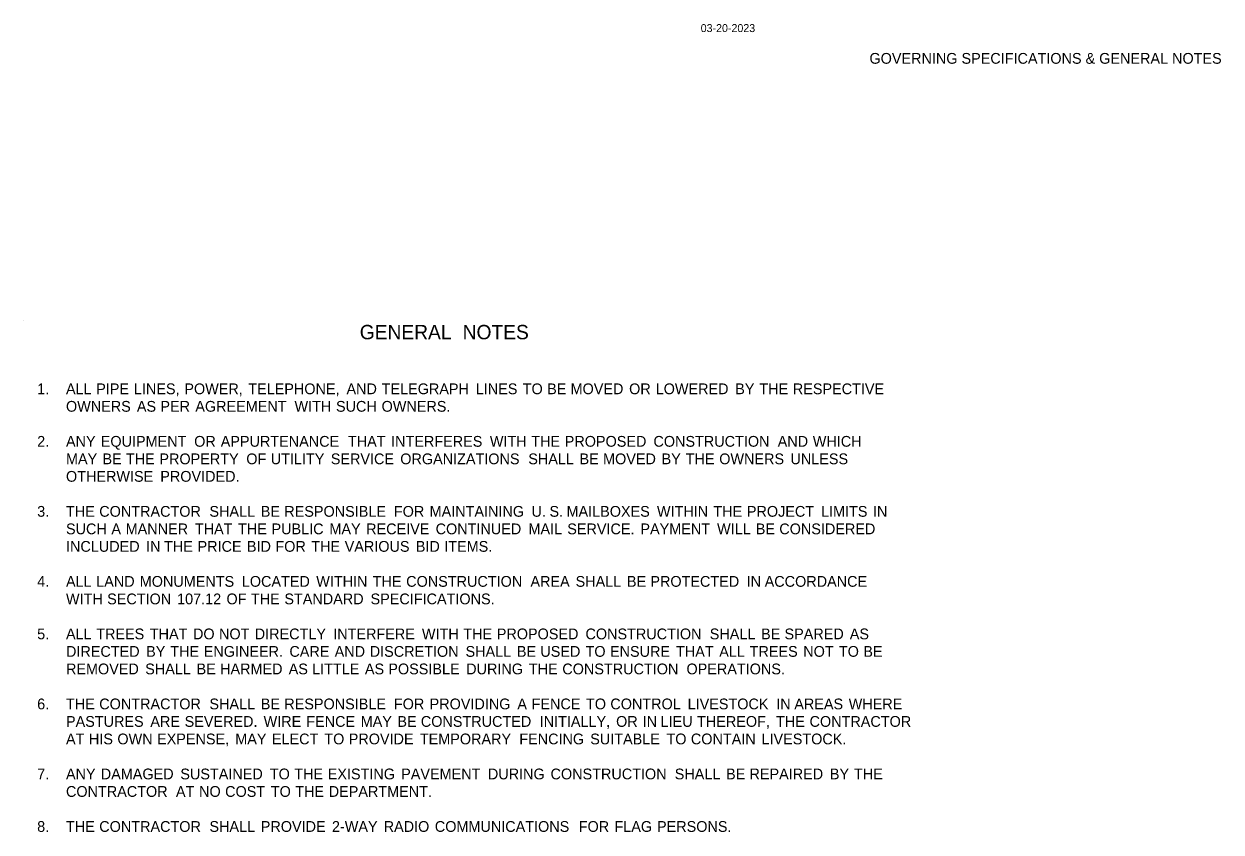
# Model space of a CAD drawing. Extents: x -1218 to 1646, y -1033 to 999.
# Drawn here: x 313 to 1646, y 98 to 999 of the extents above; entities that cross this region are included whole.
import ezdxf

# ---------------------------------------------------------------- set-up
doc = ezdxf.new("R2010")
doc.units = 0
doc.layers.add('Default', color=7, linetype='Continuous')
doc.layers.add('R_Border Prem', color=7, linetype='Continuous')

msp = doc.modelspace()

# ---------------------------------------------------------------- linework, layer by layer
at = {"layer": 'Default'}
msp.add_line((312.6, 668.5), (312.6, 668.5), dxfattribs=at)

# ---------------------------------------------------------------- texts
for s, height, p in [('GENERAL', 16, (686.6, 647.3)), (' NOTES', 16, (795.3, 647.3)), ('1.', 12, (327.3, 586.1)), ('ALL', 12, (359.4, 586.1)), (' PIPE', 12, (388.6, 586.1)), (' LINES,', 12, (430.6, 586.1)), (' POWER,', 12, (486.8, 586.1)), (' TELEPHONE,', 12, (558, 586.1)), (' AND', 12, (667.4, 586.1)), (' TELEGRAPH', 12, (706.6, 586.1)), (' LINES', 12, (811.4, 586.1)), (' TO', 12, (863.7, 586.1)), (' BE', 12, (890.9, 586.1)), (' MOVED', 12, (917, 586.1)), (' OR', 12, (982.2, 586.1)), (' LOWERED', 12, (1011.8, 586.1)), (' BY', 12, (1100.4, 586.1)), (' THE', 12, (1127.3, 586.1)), (' RESPECTIVE', 12, (1164.6, 586.1)), ('OWNERS', 12, (359.4, 566.6)), (' AS', 12, (433.9, 566.6)), (' PER', 12, (460.1, 566.6)), (' AGREEMENT', 12, (499, 566.6)), (' WITH', 12, (609.5, 566.6)), (' SUCH', 12, (655.7, 566.6)), (' OWNERS.', 12, (706.5, 566.6)), ('2.', 12, (327.3, 527.6)), ('ANY', 12, (359.4, 527.6)), (' EQUIPMENT', 12, (393.7, 527.6)), (' OR', 12, (497.7, 527.6)), (' APPURTENANCE', 12, (527.3, 527.6)), (' THAT', 12, (669, 527.6)), (' INTERFERES', 12, (717.1, 527.6)), (' WITH', 12, (827.1, 527.6)), (' THE', 12, (873.2, 527.6)), (' PROPOSED', 12, (910.5, 527.6)), (' CONSTRUCTION', 12, (1009.3, 527.6)), (' AND', 12, (1147.7, 527.6)), (' WHICH', 12, (1186.8, 527.6)), ('MAY', 12, (359.4, 508.1)), (' BE', 12, (395.6, 508.1)), (' THE', 12, (421.7, 508.1)), (' PROPERTY', 12, (459, 508.1)), (' OF', 12, (555.8, 508.1)), (' UTILITY', 12, (583, 508.1)), (' SERVICE', 12, (649.9, 508.1)), (' ORGANIZATIONS', 12, (727.3, 508.1)), (' SHALL', 12, (869.9, 508.1)), (' BE', 12, (927, 508.1)), (' MOVED', 12, (953.2, 508.1)), (' BY', 12, (1018.4, 508.1)), (' THE', 12, (1045.3, 508.1)), (' OWNERS', 12, (1082.6, 508.1)), (' UNLESS', 12, (1161.9, 508.1)), ('OTHERWISE', 12, (359.4, 488.6)), (' PROVIDED.', 12, (460, 488.6)), ('3.', 12, (327.3, 449.6)), ('THE', 12, (359.4, 449.6)), (' CONTRACTOR', 12, (392, 449.6)), (' SHALL', 12, (514.7, 449.6)), (' BE', 12, (571.9, 449.6)), (' RESPONSIBLE', 12, (598.1, 449.6)), (' FOR', 12, (720.2, 449.6)), (' MAINTAINING', 12, (760, 449.6)), (' U.', 12, (873.5, 449.6)), (' S.', 12, (893.5, 449.6)), (' MAILBOXES', 12, (912.5, 449.6)), (' WITHIN', 12, (1013.2, 449.6)), (' THE', 12, (1076.1, 449.6)), (' PROJECT', 12, (1113.4, 449.6)), (' LIMITS', 12, (1196, 449.6)), (' IN', 12, (1253.8, 449.6)), ('SUCH', 12, (359.4, 430.1)), (' A', 12, (405.5, 430.1)), (' MANNER', 12, (421.4, 430.1)), (' THAT', 12, (498.5, 430.1)), (' THE', 12, (546.6, 430.1)), (' PUBLIC', 12, (583.9, 430.1)), (' MAY', 12, (648.4, 430.1)), (' RECEIVE', 12, (689.3, 430.1)), (' CONTINUED', 12, (766.7, 430.1)), (' MAIL', 12, (870.1, 430.1)), (' SERVICE.', 12, (913.3, 430.1)), (' PAYMENT', 12, (994.8, 430.1)), (' WILL', 12, (1080.2, 430.1)), (' BE', 12, (1123.3, 430.1)), (' CONSIDERED', 12, (1149.5, 430.1)), ('INCLUDED', 12, (359.4, 410.6)), (' IN', 12, (444.2, 410.6)), (' THE', 12, (464.2, 410.6)), (' PRICE', 12, (501.5, 410.6)), (' BID', 12, (556.5, 410.6)), (' FOR', 12, (588.2, 410.6)), (' THE', 12, (628.1, 410.6)), (' VARIOUS', 12, (665.4, 410.6)), (' BID', 12, (744.6, 410.6)), (' ITEMS.', 12, (776.3, 410.6)), ('4.', 12, (327.3, 371.6)), ('ALL', 12, (359.4, 371.6)), (' LAND', 12, (388.6, 371.6)), (' MONUMENTS', 12, (437.1, 371.6)), (' LOCATED', 12, (550.8, 371.6)), (' WITHIN', 12, (633.7, 371.6)), (' THE', 12, (696.6, 371.6)), (' CONSTRUCTION', 12, (733.9, 371.6)), (' AREA', 12, (872.3, 371.6)), (' SHALL', 12, (922.6, 371.6)), (' BE', 12, (979.8, 371.6)), (' PROTECTED', 12, (1005.9, 371.6)), (' IN', 12, (1113.1, 371.6)), (' ACCORDANCE', 12, (1133.2, 371.6)), ('WITH', 12, (359.4, 352.1)), (' SECTION', 12, (400.8, 352.1)), (' 107.12', 12, (478.7, 352.1)), (' OF', 12, (533.7, 352.1)), (' THE', 12, (560.9, 352.1)), (' STANDARD', 12, (598.2, 352.1)), (' SPECIFICATIONS.', 12, (694.2, 352.1)), ('5.', 12, (327.3, 313.1)), ('ALL', 12, (359.4, 313.1)), (' TREES', 12, (388.6, 313.1)), (' THAT', 12, (448.3, 313.1)), (' DO', 12, (496.4, 313.1)), (' NOT', 12, (525.4, 313.1)), (' DIRECTLY', 12, (565.2, 313.1)), (' INTERFERE', 12, (652.6, 313.1)), (' WITH', 12, (751.4, 313.1)), (' THE', 12, (797.5, 313.1)), (' PROPOSED', 12, (834.8, 313.1)), (' CONSTRUCTION', 12, (933.6, 313.1)), (' SHALL', 12, (1072, 313.1)), (' BE', 12, (1129.2, 313.1)), (' SPARED', 12, (1155.3, 313.1)), (' AS', 12, (1228, 313.1)), ('DIRECTED', 12, (359.4, 293.6)), (' BY', 12, (444.2, 293.6)), (' THE', 12, (471.1, 293.6)), (' ENGINEER.', 12, (508.4, 293.6)), (' CARE', 12, (603.8, 293.6)), (' AND', 12, (654.2, 293.6)), (' DISCRETION', 12, (693.3, 293.6)), (' SHALL', 12, (800, 293.6)), (' BE', 12, (857.2, 293.6)), (' USED', 12, (883.3, 293.6)), (' TO', 12, (933.7, 293.6)), (' ENSURE', 12, (960.9, 293.6)), (' THAT', 12, (1034.5, 293.6)), (' ALL', 12, (1082.6, 293.6)), (' TREES', 12, (1116.5, 293.6)), (' NOT', 12, (1176.2, 293.6)), (' TO', 12, (1215.9, 293.6)), (' BE', 12, (1243.1, 293.6)), ('REMOVED', 12, (359.4, 274.1)), (' SHALL', 12, (443.2, 274.1)), (' BE', 12, (500.4, 274.1)), (' HARMED', 12, (526.6, 274.1)), (' AS', 12, (603, 274.1)), (' LITTLE', 12, (629.1, 274.1)), (' AS', 12, (687.9, 274.1)), (' POSSIBLE', 12, (714, 274.1)), (' DURING', 12, (800.7, 274.1)), (' THE', 12, (870.5, 274.1)), (' CONSTRUCTION', 12, (907.8, 274.1)), (' OPERATIONS.', 12, (1046.1, 274.1)), ('6.', 12, (327.3, 235.1)), ('THE', 12, (359.4, 235.1)), (' CONTRACTOR', 12, (392, 235.1)), (' SHALL', 12, (514.7, 235.1)), (' BE', 12, (571.9, 235.1)), (' RESPONSIBLE', 12, (598.1, 235.1)), (' FOR', 12, (720.2, 235.1)), (' PROVIDING', 12, (760, 235.1)), (' A', 12, (857.7, 235.1)), (' FENCE', 12, (873.6, 235.1)), (' TO', 12, (934.2, 235.1)), (' CONTROL', 12, (961.3, 235.1)), (' LIVESTOCK', 12, (1047.4, 235.1)), (' IN', 12, (1146.1, 235.1)), (' AREAS', 12, (1166.2, 235.1)), (' WHERE', 12, (1226.8, 235.1)), ('PASTURES', 12, (359.4, 215.6)), (' ARE', 12, (448.9, 215.6)), (' SEVERED.', 12, (487.1, 215.6)), (' WIRE', 12, (575.1, 215.6)), (' FENCE', 12, (622.6, 215.6)), (' MAY', 12, (683.2, 215.6)), (' BE', 12, (724.1, 215.6)), (' CONSTRUCTED', 12, (750.2, 215.6)), (' INITIALLY,', 12, (882.6, 215.6)), (' OR', 12, (967.7, 215.6)), (' IN', 12, (997.3, 215.6)), (' LIEU', 12, (1017.3, 215.6)), (' THEREOF,', 12, (1057.9, 215.6)), (' THE', 12, (1145.9, 215.6)), (' CONTRACTOR', 12, (1183.2, 215.6)), ('AT', 12, (359.4, 196.1)), (' HIS', 12, (380.5, 196.1)), (' OWN', 12, (412.2, 196.1)), (' EXPENSE,', 12, (456.4, 196.1)), (' MAY', 12, (543.5, 196.1)), (' ELECT', 12, (584.3, 196.1)), (' TO', 12, (642.7, 196.1)), (' PROVIDE', 12, (669.9, 196.1)), (' TEMPORARY', 12, (749.1, 196.1)), (' FENCING', 12, (859.9, 196.1)), (' SUITABLE', 12, (938.9, 196.1)), (' TO', 12, (1023.8, 196.1)), (' CONTAIN', 12, (1051, 196.1)), (' LIVESTOCK.', 12, (1129.7, 196.1)), ('7.', 12, (327.3, 157.1)), ('ANY', 12, (359.4, 157.1)), (' DAMAGED', 12, (393.7, 157.1)), (' SUSTAINED', 12, (482.3, 157.1)), (' TO', 12, (582, 157.1)), (' THE', 12, (609.2, 157.1)), (' EXISTING', 12, (646.5, 157.1)), (' PAVEMENT', 12, (728.3, 157.1)), (' DURING', 12, (824.9, 157.1)), (' CONSTRUCTION', 12, (894.7, 157.1)), (' SHALL', 12, (1033, 157.1)), (' BE', 12, (1090.2, 157.1)), (' REPAIRED', 12, (1116.3, 157.1)), (' BY', 12, (1205.8, 157.1)), (' THE', 12, (1232.7, 157.1)), ('CONTRACTOR', 12, (359.4, 137.6)), (' AT', 12, (477.4, 137.6)), (' NO', 12, (503.2, 137.6)), (' COST', 12, (532.2, 137.6)), (' TO', 12, (583.1, 137.6)), (' THE', 12, (610.3, 137.6)), (' DEPARTMENT.', 12, (647.6, 137.6)), ('8.', 12, (327.3, 98.6)), ('THE', 12, (359.4, 98.6)), (' CONTRACTOR', 12, (392, 98.6)), (' SHALL', 12, (514.7, 98.6)), (' PROVIDE', 12, (571.9, 98.6)), (' 2-WAY', 12, (651.2, 98.6)), (' RADIO', 12, (708.8, 98.6)), (' COMMUNICATIONS', 12, (765.8, 98.6)), (' FOR', 12, (926.1, 98.6)), (' FLAG', 12, (965.9, 98.6)), (' PERSONS.', 12, (1013.3, 98.6))]:
    msp.add_text(s, height=height, dxfattribs=at).set_placement(p)
at = {"layer": 'R_Border Prem'}
for s, height, p in [('03-20-2023', 8.87, (1066.4, 989.5)), ('GOVERNING SPECIFICATIONS & GENERAL NOTES', 12, (1254.4, 954.2))]:
    msp.add_text(s, height=height, dxfattribs=at).set_placement(p)

doc.saveas('drawing.dxf')
